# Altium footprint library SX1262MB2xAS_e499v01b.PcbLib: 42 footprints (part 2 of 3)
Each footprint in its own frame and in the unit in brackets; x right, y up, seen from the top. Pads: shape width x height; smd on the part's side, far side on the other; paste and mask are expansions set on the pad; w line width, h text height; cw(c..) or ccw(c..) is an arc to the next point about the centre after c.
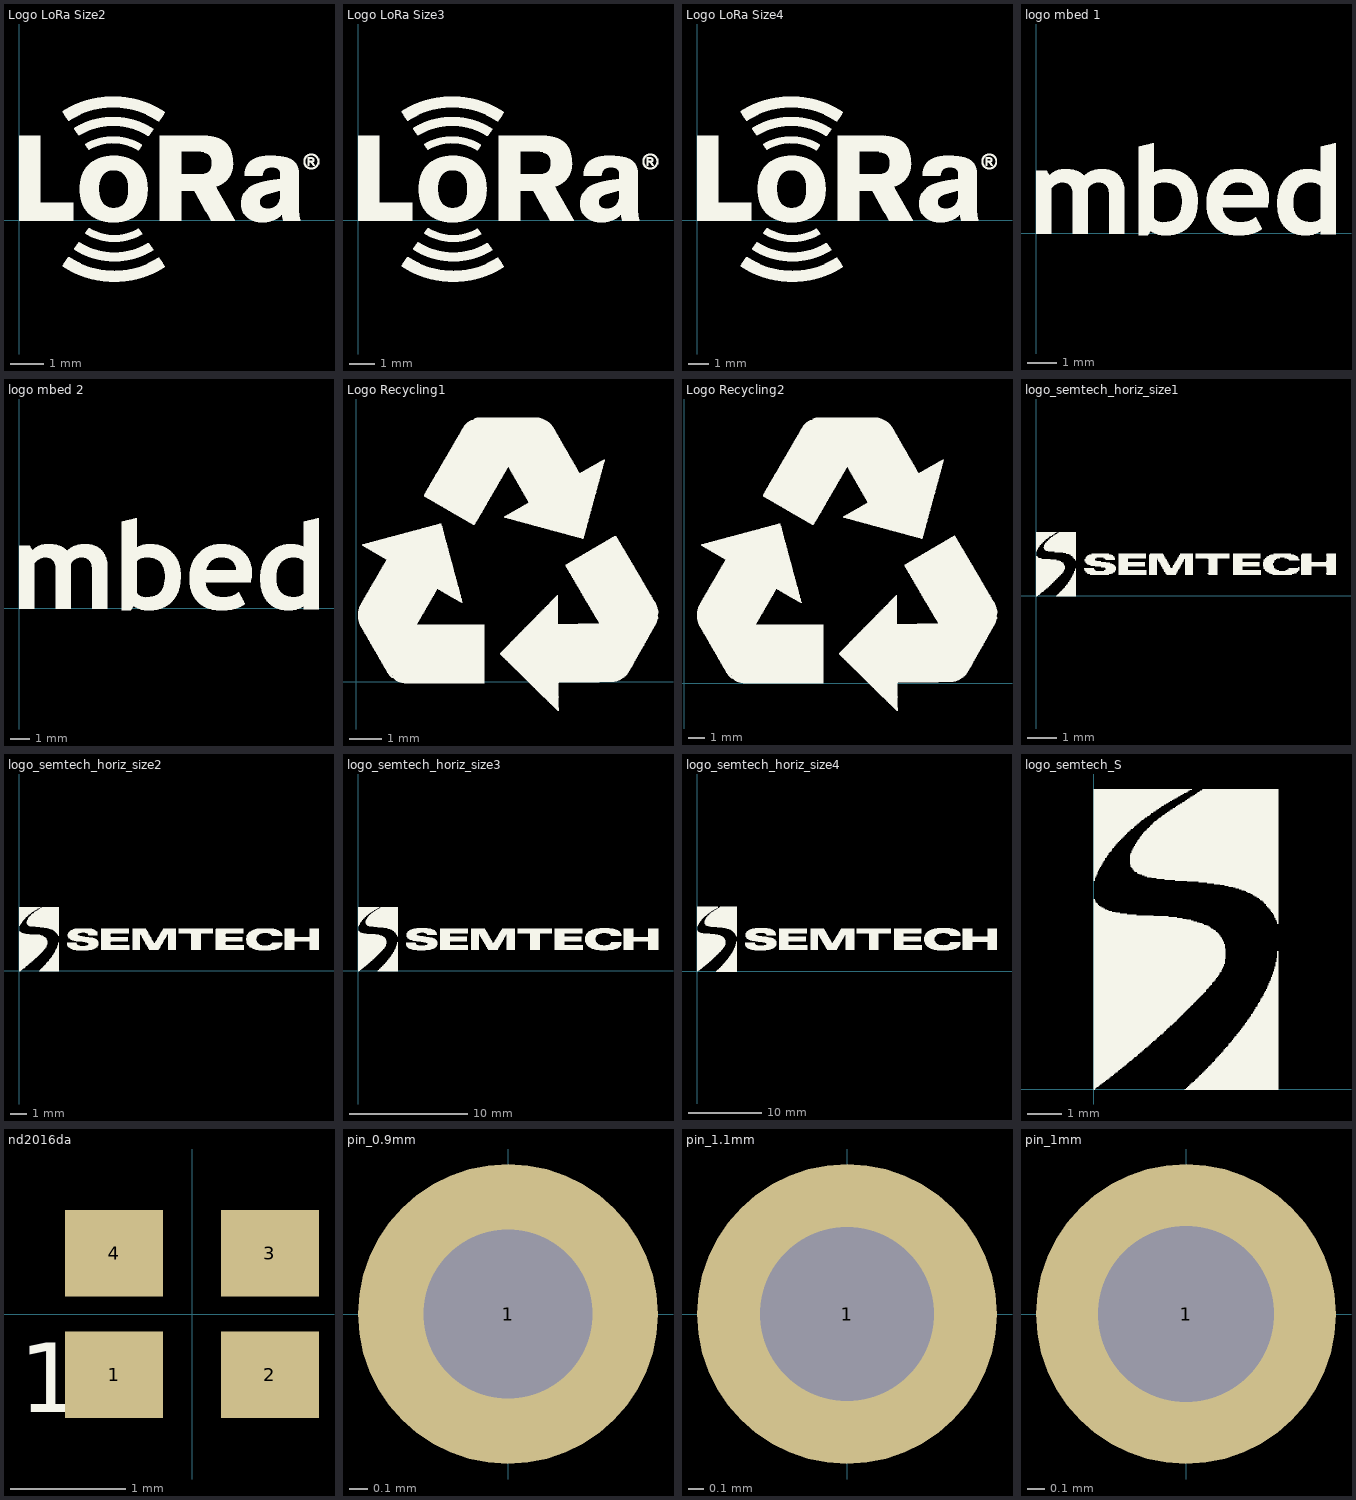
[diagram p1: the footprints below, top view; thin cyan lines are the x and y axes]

## Logo LoRa Size2 [mm] "Logo LoRa Size2 - Top Overlay - 9x5.5mm - Registered"
Top Overlay:
  drawing of 1298 lines, arcs and shapes, not listed

## Logo LoRa Size3 [mm] "Logo LoRa Size3 - Top Overlay - 14.5x8mm - Registered"
Top Overlay:
  drawing of 1298 lines, arcs and shapes, not listed
3D body: height 0.8, standoff 0.1, extent 2.3,-0.1 5.25,2.65

## Logo LoRa Size4 [mm] "Logo LoRa Size4 - Top Overlay - 18x9.5mm - Registered"
Top Overlay:
  drawing of 1298 lines, arcs and shapes, not listed

## logo mbed 1 [mm] "logo mbed 1"
height 0.2
Top Overlay:
  drawing of 1792 lines, arcs and shapes, not listed

## logo mbed 2 [mm] "logo mbed 2"
height 0.2
Top Overlay:
  drawing of 1792 lines, arcs and shapes, not listed

## Logo Recycling1 [mm] "Logo Recycling1"
height 0.1
Top Overlay:
  drawing of 3302 lines, arcs and shapes, not listed

## Logo Recycling2 [mm] "Logo Recycling2"
height 0.1
Top Overlay:
  drawing of 3309 lines, arcs and shapes, not listed

## logo_semtech_horiz_size1 [mm] "Logo semtech horizontal - size1 - S"
Top Overlay:
  drawing of 453 lines, arcs and shapes, not listed

## logo_semtech_horiz_size2 [mm] "Logo semtech horizontal - size2 - M"
Top Overlay:
  drawing of 790 lines, arcs and shapes, not listed

## logo_semtech_horiz_size3 [mm] "Logo semtech horizontal - size3 - L"
Top Overlay:
  drawing of 1137 lines, arcs and shapes, not listed

## logo_semtech_horiz_size4 [mm] "Logo semtech horizontal - size4 - XL"
Top Overlay:
  drawing of 1852 lines, arcs and shapes, not listed

## logo_semtech_S [mm] "Logo semtech S size4 - XL"
Top Overlay:
  drawing of 642 lines, arcs and shapes, not listed

## nd2016da [mm] "Crystal SMD 2.0x1.6mm"
height 0.55
pads (4):
  rect 0.85x0.75 smd mask+0.05: 1(-0.675,-0.525) 2(0.675,-0.525) 3(0.675,0.525) 4(-0.675,0.525)
Top Overlay:
  text "1" at -1.5,-0.85 h0.6
3D body: height 1, standoff 0, extent -1,-0.8 1,0.8

## pin_0.9mm [mm] "Generic Pin 0.9mm; 1 Lead"
height 1
pads (1):
  round 1.6 hole 0.9 mask+0.05: 1(0,0)

## pin_1.1mm [mm] "Generic Pin 1.1mm; 1 Lead"
height 1
pads (1):
  round 1.9 hole 1.1 mask+0.05: 1(0,0)

## pin_1mm [mm] "Generic Pin 1.1mm; 1 Lead"
height 1
pads (1):
  round 1.7 hole 1 paste+0 mask+0.05: 1(0,0)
